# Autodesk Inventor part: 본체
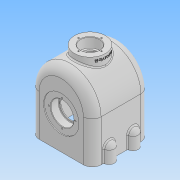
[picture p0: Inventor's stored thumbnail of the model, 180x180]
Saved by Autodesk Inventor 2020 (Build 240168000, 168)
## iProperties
Created: 2023-03
Part Number: 본체
Material: 일반
Document SubType Name: Modeling
Designer: user
Density: 1 g/cm^3
Appearance: 기본값
Mass: 844.028 g
Surface Area: 1798.4 cm^2
Volume: 844.028 cm^3
Author: user
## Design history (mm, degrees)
sketch "스케치1"
  geometry: L1 (70, 94)-(70, 0); L2 (70, 0)-(-70, 0); L3 (-70, 0)-(-70, 94); A1 r 70 centre (0, 94) between (70, 94) and (-70, 94); 2 further points
  constraints: 6 end point, 2 point on circle, 1 centre point, 1 coincident, 1 midpoint, 1 parallel
  dimensions: "d0" = 140 diameter of A1; "d1" = 94 distance of point (0, 0) A1.centre
extrude "돌출1" new body sketch "스케치1" stored distance "d2" = 130; taper "d3" = 0 deg
fillet "모깎기1" dims "d4" = 20
feature "쉘1" dims "d5" = 10
sketch "스케치2"
  geometry: L1 (144, -65)-(0, -65) reference; L2 (0, -65)-(0, -55) reference; L3 (0, -55)-(144, -55) reference; L4 (154, -45)-(154, 45) reference; L5 (144, 55)-(0, 55) reference; L6 (0, 55)-(0, 65) reference; L7 (0, 65)-(144, 65) reference; L8 (164, 45)-(164, -45) reference; L9 (75, -43)-(75, -65); L10 (98, -65)-(117, -65); L11 (117, -65)-(117, -55); L12 (144, -55)-(94, -55) reference; L13 (117, -55)-(105, -43); L14 (105, -43)-(98, -43); L15 (94, -45)-(94, 45) reference; L16 (98, -43)-(98, -65); L17 (94, -65)-(0, -65) reference; L18 (85.853, 0)-(62, 0); A1 r 20 centre (144, -45) between (144, -65) and (164, -45) reference; A2 r 10 centre (144, -45) between (144, -55) and (154, -45) reference; A3 r 10 centre (144, 45) between (154, 45) and (144, 55) reference; A4 r 20 centre (144, 45) between (164, 45) and (144, 65) reference; 1 further point
  constraints: 14 end point, 4 point on line, 3 perpendicular, 1 horizontal, 1 horizontal alignment, 1 vertical
  dimensions: "d6" = 60 diameter of L13.end L9; "d7" = 135 deg angle of L12 L13; "d8" = 22 distance of L14.end L10.start; "d9" = 75 horizontal distance of L2.end L9.end; "d10" = 46 diameter of L16 L9
revolve "회전1" sketch "스케치2" stored, may be unused: angle "d11" = 90 deg
sketch "스케치3"
  geometry: L1 (-50, 0)-(50, 0) reference; 3 further points
  constraints: 1 midpoint, 1 vertical alignment
  dimensions: "d12" = 75 distance of point (0, 0) point (0, 75)
hole "구멍1" sketch "스케치3" at (0, 75) diameter "d13" = 46; stored, may be unused: countersink angle "d17" = 90 deg, drill point angle "d19" = 118 deg; dims "d14" = 6, "d15" = 52, "d16" = 20, "d18" = 30
sketch "스케치4"
  geometry: C1 r 26 at (0, 75) reference; 1 further point
hole "구멍2" sketch "스케치4" at (0, 75) diameter "d20" = 80; stored, may be unused: countersink angle "d24" = 90 deg, drill point angle "d26" = 0 deg; dims "d21" = 6, "d22" = 52, "d23" = 20, "d25" = 2
sketch "스케치5"
  geometry: C1 r 40 at (0, 0) reference; C2 r 26 at (0, 0) reference; C3 r 30 at (0, 0); 6 further points
  constraints: 2 vertical alignment, 1 centre point, 1 coincident, 6 other
  dimensions: "d27" = 60 diameter of C3; "d30" = 360 deg dimension on C3.centre point (0, 30) (derived)
hole "구멍3" sketch "스케치5" at (0, 30), (30, 0), (0, -30), (-30, 0) diameter "d32" = 3.242; stored, may be unused: countersink angle "d36" = 90 deg, drill point angle "d38" = 118 deg; dims "d33" = 8, "d34" = 52, "d35" = 20, "d37" = 10
node "작업 평면1"
sketch "스케치6"
  geometry: C1 r 35 at (50, -65); 1 further point
  constraints: 1 centre point, 1 coincident
  dimensions: "d40" = 70 diameter of C1
extrude "돌출2" join sketch "스케치6" stored distance "d41" = 130; taper "d42" = 0 deg
sketch "스케치7"
  geometry: C1 r 35 at (0, 0) reference; 2 further points
  constraints: 1 coincident
hole "구멍4" sketch "스케치7" at (0, 0) diameter "d43" = 34; stored, may be unused: countersink angle "d47" = 90 deg, drill point angle "d49" = 118 deg; dims "d44" = 8, "d45" = 43, "d46" = 22, "d48" = 10
sketch "스케치8" dims "d50" = 52
  geometry: C1 r 21.5 at (0, 0) reference; C2 r 35 at (0, 0) reference; 5 further points
  constraints: 2 vertical alignment, 1 coincident, 7 other
  dimensions: "d53" = 360 deg dimension on point (0, 0) point (0, 26) (derived)
hole "구멍5" sketch "스케치8" at (0, 26), (-26, 0), (0, -26), (26, 0) diameter "d55" = 3.242; stored, may be unused: countersink angle "d59" = 90 deg, drill point angle "d61" = 118 deg; dims "d56" = 8, "d57" = 43, "d58" = 22, "d60" = 10
sketch "스케치9"
  geometry: L1 (110, -20)-(110, -110) reference; L2 (-10, -110)-(-10, -20) reference; L3 (120, -20)-(120, -110) reference; L4 (-20, -110)-(-20, -20) reference; L5 (-10, -31.367)-(-10, -44.633); L6 (-10, -85.367)-(-10, -98.633); L7 (110, -85.367)-(110, -98.633); L8 (110, -31.367)-(110, -44.633); L9 (110, -110)-(110, -20) reference; A1 r 12 centre (-20, -38) between (-10, -31.367) and (-10, -44.633); A2 r 12 centre (-20, -92) between (-10, -85.367) and (-10, -98.633); A3 r 12 centre (120, -38) between (110, -44.633) and (110, -31.367); A4 r 12 centre (120, -92) between (110, -98.633) and (110, -85.367); 2 further points
  constraints: 13 point on line, 8 end point, 8 point on circle, 4 centre point, 2 collinear, 2 horizontal alignment, 1 parallel
  dimensions: "d62" = 24 diameter of A1; "d63" = 24 diameter of A2; "d64" = 24 diameter of A3; "d65" = 24 diameter of A4; "d66" = 54 distance of A4.centre A3.centre; "d67" = 27 vertical distance of point (50, -65) A3.centre
extrude "돌출3" join sketch "스케치9" distance "d68" = 28; taper "d69" = 0 deg
sketch "스케치12"
  geometry: L1 (120, 50)-(120, 26) reference; L2 (120, 80)-(120, 50) reference; L3 (120, 110)-(120, 104) reference; L4 (0, 130)-(100, 130) reference; L5 (-20, 104)-(-20, 110) reference; L6 (-20, 80)-(-20, 104) reference; L7 (120, 26)-(120, 20) reference; L8 (100, 0)-(0, 0) reference; L9 (-20, 20)-(-20, 26) reference; L10 (-20, 26)-(-20, 50) reference; L11 (120, 104)-(120, 80) reference; L12 (-20, 50)-(-20, 80) reference; L13 (100, 120)-(0, 120) reference; L14 (-10, 110)-(-10, 20) reference; L15 (0, 10)-(100, 10) reference; L16 (110, 20)-(110, 110) reference; L17 (120, 38)-(132, 38); L18 (120, 50)-(120, 80) reference; L19 (120, 50)-(120, 38); A1 r 12 centre (120, 38) between (120, 26) and (120, 50) reference; A2 r 12 centre (120, 92) between (120, 80) and (120, 104) reference; A3 r 20 centre (100, 110) between (120, 110) and (100, 130) reference; A4 r 20 centre (0, 110) between (0, 130) and (-20, 110) reference; A5 r 12 centre (-20, 92) between (-20, 104) and (-20, 80) reference; A6 r 20 centre (100, 20) between (100, 0) and (120, 20) reference; A7 r 20 centre (0, 20) between (-20, 20) and (0, 0) reference; A8 r 12 centre (-20, 38) between (-20, 50) and (-20, 26) reference; A9 r 10 centre (0, 110) between (0, 120) and (-10, 110) reference; A10 r 10 centre (0, 20) between (-10, 20) and (0, 10) reference; A11 r 10 centre (100, 20) between (100, 10) and (110, 20) reference; A12 r 10 centre (100, 110) between (110, 110) and (100, 120) reference; A13 r 12 centre (120, 38) between (120, 26) and (120, 50); A14 r 12 centre (120, 38) between (120, 26) and (120, 50) reference; 2 further points
  constraints: 4 end point, 4 point on circle, 2 point on line, 1 centre point, 1 coincident
  dimensions: "d71" = 24 diameter of A13
revolve "회전2" sketch "스케치12" stored, may be unused: angle "d72" = 90 deg
sketch "스케치13"
  geometry: A1 r 12 centre (120, 38) between (120, 26) and (120, 50) reference; A2 r 12 centre (120, 92) between (120, 80) and (120, 104) reference; A3 r 12 centre (-20, 92) between (-20, 104) and (-20, 80) reference; A4 r 12 centre (-20, 38) between (-20, 50) and (-20, 26) reference; 1 further point
hole "구멍6" sketch "스케치13" at (120, 92), (120, 38), (-20, 38), (-20, 92) diameter "d73" = 10.106; stored, may be unused: countersink angle "d77" = 90 deg, drill point angle "d79" = 118 deg; dims "d74" = 24, "d75" = 43, "d76" = 22, "d78" = 26
node "작업 평면2"
sketch "스케치14"
  geometry: L1 (-1.449, 25.069)-(-1.449, -25.069); L2 (-1.449, -25.069)-(-14.551, -25.069); L3 (-14.551, -25.069)-(-14.551, 25.069); L4 (-14.551, 25.069)-(-1.449, 25.069); L5 (-8, 25.069)-(-8, -25.069); L6 (-1.449, 0)-(-14.551, 0); L7 (-178, 15)-(-178, -15) reference; L8 (0, 35)-(0, -35) reference; 2 further points
  constraints: 5 midpoint, 4 end point, 1 horizontal alignment, 1 vertical, 2 other
  dimensions: "d80" = 8 distance between parallel lines of L5 L8
feature "엠보싱1" sketch "스케치14" dims "d0" = 140, "d1" = 94, "d6" = 60, "d7" = 135 deg, "d8" = 22, "d9" = 75, "d10" = 46, "d81" = 0.5, "d82" = 0
chamfer "모따기1" distance "d83" = 1; stored, may be unused: second distance "d84" = 2, angle "d85" = 45 deg
fillet "모깎기2" dims "d86" = 1
fillet "모깎기3" dims "d87" = 3
fillet "모깎기4" dims "d88" = 3
node "솔리드1"
mirror "미러1"
mirror "미러2"
mirror "미러3"
mirror "미러4"
node "절단 모서리 투영1"
node "절단 모서리 투영3"
feature "A9D066F2-1C7D-4E18-AEED-F7BC21143FA4" dims "d13" = 46, "d14" = 6, "d15" = 52, "d16" = 20, "d17" = 90 deg, "d18" = 30, "d19" = 118 deg
other parameters: "d39" = -178
